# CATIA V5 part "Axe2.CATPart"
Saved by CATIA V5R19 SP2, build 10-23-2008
Part number: Axe.1
Publications: "Dac"
Bounding box of the stored display mesh (mm): x 0 to 200, y -7.5 to 7.5, z -7.49 to 7.49
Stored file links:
  C:\Users\Vianney\Documents\Garantie\Cours\2A\IAO\IAO-proj-Catia\Axe2.CATPart
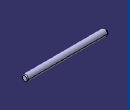
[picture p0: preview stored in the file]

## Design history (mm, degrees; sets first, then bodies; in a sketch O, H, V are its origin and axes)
Parameters
  Dac = 15 mm
  Laxec = 200 mm
Body1 (main body)
  Sketch1 on yz-plane, origin (0, 0, 0), H (0, 1, 0), V (0, 0, 1)
    circle A1 centre (0, 0) radius 7.5
    radius A1 = 7.5 {= Dac /2}
  Pad1: profile Sketch1, direction (1, 0, 0), length 200 {= Laxec}
  Fillet1: radius 2, on edge [face of Pad1 from Sketch1.A1 | end face of Pad1]; edge [start face of Pad1 | face of Pad1 from Sketch1.A1]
